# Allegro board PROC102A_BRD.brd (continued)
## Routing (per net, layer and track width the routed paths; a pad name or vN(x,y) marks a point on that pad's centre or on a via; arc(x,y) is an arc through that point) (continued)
EN_PHY_8: length 198.5
  TOP w0.152: v1(100.47,143.59) 100.38,143.51 98.64,143.51 TP30.1
  L03_SIG1 w0.152: v1(100.47,143.59) 100.76,143.59 102.74,141.6 106.94,141.6 108.58,139.96 108.84,139.7 108.84,139.7 109.73,138.81 111.38,138.81 113.41,136.78 113.41,106.65 99.85,93.09 99.85,76.43 103.76,72.52 103.76,57.78 92.76,46.79 92.76,42.3 90.42,39.95 73.84,39.95 71.81,37.92 71.81,37.79 71.55,37.54 71.43,37.54 69.22,35.33 69.22,31.88 66.5,29.16 59.77,29.16 59.13,28.52 46.23,28.52 44.83,29.92 42.67,29.92 41.15,28.4 v1(41.15,26.67)
  BOTTOM w0.152: v1(100.47,143.59) 100.73,143.85 105.44,143.85 107.45,141.85 U34.5 ; U9.25 v1(41.15,26.67)
FAULT_1: length 187.3
  TOP w0.152: v1(126.11,127.25) 123.38,124.52 v1(105.09,124.52)
  L03_SIG1 w0.152: v1(105.09,124.52) 99.56,118.99 79.49,118.99 69.35,108.84 65.48,108.84 61.77,105.13 61.77,90.86 59.06,88.14 52.45,88.14 47.42,83.11 47.42,43.21 37.37,33.16 37.37,26.42 v1(36.93,25.98)
  BOTTOM w0.152: U27.2 132.24,140.66 R76.1 132.12,140.1 131.96,139.93 130.48,139.93 130.22,139.67 130.22,131.36 v1(126.11,127.25) ; U11.45 36.43,26.48 v1(36.93,25.98)
FAULT_2: length 190.2
  TOP w0.152: v1(97.54,119.76) 113.52,119.76 v1(127.53,105.75)
  L03_SIG1 w0.152: v1(36.91,24.79) 36.5,25.2 36.5,32.72 47.12,43.34 47.12,83.95 52.71,89.54 59.31,89.54 61.22,91.44 61.22,105.28 65.79,109.86 69.35,109.86 79.25,119.76 v1(97.54,119.76)
  BOTTOM w0.152: U28.2 132.13,115.2 R77.1 132.01,114.63 131.76,114.38 130.35,114.38 129.54,113.57 129.54,107.76 v1(127.53,105.75) ; U11.44 35.93,25.76 v1(36.91,24.79)
FAULT_3: length 154.4
  L03_SIG1 w0.152: v1(33.93,25.98) 34,25.91 34,24.71 35.47,23.25 52.46,23.25 53.14,23.93 66.8,23.93 68.2,25.32 72.75,25.32 73.99,26.57 73.99,30.48 76.41,32.89 98.17,32.89 128.4,63.12 131.32,63.12 133.35,65.15 133.35,68.45 129.54,72.26 129.54,89.79 130.35,90.6 v1(131.43,90.6)
  BOTTOM w0.152: v1(131.43,90.6) 132.01,90.02 R83.1 132.13,89.8 U30.2 ; v1(33.93,25.98) 33.43,26.48 U11.39
FAULT_4: length 123.1
  L03_SIG1 w0.152: v1(35.41,23.92) 35.77,23.55 51.81,23.55 52.49,24.23 66.65,24.23 68.07,25.65 71.76,25.65 73.66,27.56 73.66,30.58 77.24,34.16 98.55,34.16 129.08,64.69 v1(131.85,64.69)
  BOTTOM w0.152: v1(131.85,64.69) 132.14,64.41 R81.1 132.25,64.02 U29.2 ; v1(35.41,23.92) 35.32,23.92 32.93,26.31 U11.38
FAULT_5: length 127.4
  TOP w0.152: v1(24.89,50.16) 26.54,51.82 26.54,59.66 27.05,60.17 27.05,68.96 27.56,69.47 100.2,69.47 v1(104.27,65.41)
  BOTTOM w0.152: U31.2 106.85,64.02 R89.1 105.23,65.41 v1(104.27,65.41) ; v1(24.89,50.16) 24.89,49.78 27.24,47.44 27.24,41.34 29.93,38.65 U11.32
FAULT_6: length 183.9
  TOP w0.152: v1(104.7,91.59) 99.03,97.36 98.32,98.07 98,98.28 95.97,100.32 v1(90.16,100.32)
  BOTTOM w0.152: v1(90.16,100.32) 90.06,100.21 76.08,100.21 75.06,99.19 70.36,99.19 67.74,96.57 65.28,96.57 58.37,89.66 12.45,89.66 8.85,86.07 8.85,59.77 9.15,59.48 9.15,41.15 25.02,25.27 28.07,25.27 29.43,26.64 U11.31 ; U32.2 106.85,89.93 R88.1 106.74,90.21 106.14,90.8 105.48,90.8 v1(104.7,91.59)
FAULT_7: length 165.2
  L03_SIG1 w0.152: v1(26.96,29.94) 31.78,29.94 34.67,27.05 34.67,26.04 35.16,25.55 35.41,25.55 36.98,23.98 38.46,23.98 39.88,25.4 39.88,27.99 43.08,31.19 47.81,31.19 49.28,29.72 55.5,29.72 55.88,30.1 55.88,31.11 56.62,31.85 59.26,31.85 60.33,30.78 65.86,30.78 67.61,32.53 67.61,37.44 72.77,42.6 72.77,46.38 76.81,50.42 81.48,50.42 91.39,60.33 91.39,109.02 100.29,117.92 105.34,117.92 106.41,116.86 106.41,115.6 v1(106.32,115.52)
  BOTTOM w0.152: v1(26.96,29.94) 26.93,29.92 U11.26 ; U33.2 106.85,114.82 R95.1 106.74,115.11 v1(106.32,115.52)
FAULT_8: length 225.4
  TOP w0.152: v1(44.95,84.21) 85.48,84.21 v1(93.6,92.33)
  L03_SIG1 w0.152: v1(44.95,84.21) 12.17,84.21 9.27,81.31 9.27,58.31 12.85,54.74 25.27,54.74 26.51,53.5 26.51,49.24 24.56,47.29 24.56,37.34 v1(23.59,36.37) ; v1(93.6,92.33) 98.43,92.33 112.9,106.81 112.9,136.4 111,138.3 108.21,138.3 106.12,140.38 v1(106.12,141.09)
  BOTTOM w0.152: U34.2 106.85,140.35 R94.1 106.74,140.48 v1(106.12,141.09) ; U11.25 26.43,29.2 23.59,32.04 v1(23.59,36.37)
GPMC0_AD0: length 26.1
  BOTTOM w0.152: U11.2 37.43,21.5 37.65,21.72 38.48,21.72 38.99,21.21 38.99,17.14 41.02,15.11 46.1,15.11 50.24,10.97 50.24,10.21 51.99,8.46 52.76,8.46 53.1,8.11 J1.E14
GPMC0_AD0_HDR: length 36.7
  BOTTOM w0.152: U11.48 37.93,33.5 35.64,35.79 35.64,35.82 35.59,35.87 35.59,60.86 J6.1
GPMC0_AD1: length 26.3
  BOTTOM w0.152: J1.D14 53.1,6.21 52.45,6.86 52.45,7.37 45.09,14.73 37.59,14.73 36.43,15.89 U11.4
GPMC0_AD1_HDR: length 37.5
  BOTTOM w0.152: U11.47 37.43,33.56 35.26,35.74 35.26,57.09 32.32,60.03 32.32,61.59 J6.3
GPMC0_AD2: length 31.7
  L03_SIG1 w0.152: v1(41.28,16.26) 42.42,16.26 52.45,6.22 v1(52.45,3.94)
  BOTTOM w0.152: v1(41.28,16.26) 39.63,17.91 39.63,21.46 38.7,22.38 37.92,22.38 37.7,22.61 34.8,22.61 34.43,22.24 U11.8 ; v1(52.45,3.94) 52.55,3.94 J1.C14
GPMC0_AD2_HDR: length 39.4
  BOTTOM w0.152: U11.42 34.93,29.09 35.18,29.34 35.97,29.34 36.58,29.94 36.58,33.99 34.95,35.62 34.95,54.46 29.47,59.94 29.47,61.9 J6.5
GPMC0_AD3: length 26.1
  BOTTOM w0.152: J1.E15 51.83,7.35 44.83,14.35 36.7,14.35 33.43,17.62 U11.10
GPMC0_AD3_HDR: length 40.4
  BOTTOM w0.152: J6.7 27.24,61.59 27.24,60.03 34.65,52.62 34.65,35.49 36.21,33.92 36.21,30.01 35.96,29.76 35.04,29.76 34.43,29.15 U11.41
GPMC0_AD4: length 30.2
  BOTTOM w0.152: J1.D15 51.83,5.83 51.18,6.48 51.18,7.57 50.24,8.51 48.52,8.51 43.31,13.72 33.78,13.72 30.93,16.57 U11.15
GPMC0_AD4_HDR: length 39.1
  BOTTOM w0.152: J6.9 23.27,62.05 22.16,60.94 22.16,54.85 29.77,47.24 29.77,41.14 31.43,39.47 U11.35
GPMC0_AD5: length 47.1
  BOTTOM w0.152: U11.17 29.93,21.88 29.34,22.48 27.94,22.48 27.05,23.37 25.78,23.37 25.27,22.86 25.27,16.46 31.66,10.07 31.66,5.75 32.31,5.11 50.88,5.11 51.49,4.49 J1.C15
GPMC0_AD5_HDR: length 39
  BOTTOM w0.152: J6.11 20.73,62.05 21.83,60.94 21.83,54.75 29.47,47.11 29.47,40.59 30.93,39.13 U11.34
GPMC0_AD6: length 31.2
  BOTTOM w0.152: U11.21 27.93,19.85 27.05,18.97 27.05,15.75 30.61,12.19 44.13,12.19 J1.E17
GPMC0_AD6_HDR: length 39.4
  BOTTOM w0.152: U11.29 28.43,38.28 24.7,42.01 24.7,47.33 19.29,52.74 19.29,62.5 18.77,63.02 J6.13
GPMC0_AD7: length 32.3
  BOTTOM w0.152: U11.23 26.93,19.29 26.75,19.1 26.75,15.62 26.93,15.44 30.69,11.68 44.2,11.68 48.59,7.29 48.59,6.46 J1.D17
GPMC0_AD7_HDR: length 39.9
  BOTTOM w0.152: U11.28 27.93,37.72 24.4,41.26 24.4,47.2 17.08,54.51 17.08,60.9 15.65,62.33 J6.15
GPMC0_AD8: length 90.9
  L03_SIG1 w0.152: J6.17 13.94,63.02 14.21,62.75 14.21,58.18 14.99,57.4 25.02,57.4 34.67,47.75 34.67,38.86 25.7,29.89 25.7,16.29 32.49,9.5 34.55,9.5 35.96,8.1 37.41,8.1 37.96,7.54 37.96,5.05 41.7,1.31 v1(42.31,1.31)
  BOTTOM w0.152: J1.A22 v1(42.31,1.31)
GPMC0_AD9: length 104.8
  L03_SIG1 w0.152: v1(43.58,1.31) 43.58,1.93 42.08,3.42 40.86,3.42 38.97,5.31 38.97,8.02 37.97,9.02 35.47,9.02 34.68,9.8 32.62,9.8 26.8,15.62 26.8,21.74 26,22.54 26,22.9 26.11,23 26.11,29.82 35.31,39.02 35.31,64.39 34.16,65.53 13.08,65.53 J6.19
  BOTTOM w0.152: J1.A21 v1(43.58,1.31)
GPMC0_AD10: length 66.2
  TOP w0.152: v1(43.58,2.58) 42.78,3.38 42.78,8.78 38.78,12.77 38.78,31.24 32.25,37.77 32.25,54.48 J7.1
  BOTTOM w0.152: J1.B21 v1(43.58,2.58)
GPMC0_AD11: length 60.3
  TOP w0.152: J7.3 34.57,54.27 34.57,36.34 39.13,31.79 39.13,13.17 43.43,8.86 v1(43.43,7.66)
  BOTTOM w0.508: v1(43.43,7.66) 44.07,7.03 J1.E21
GPMC0_AD12: length 65.4
  TOP w0.152: v1(43.58,3.85) 43.15,4.29 43.15,6.73 43.86,7.45 43.86,8.86 39.43,13.29 39.43,32.37 34.88,36.92 34.88,52.03 J7.5
  BOTTOM w0.152: J1.C21 v1(43.58,3.85)
GPMC0_AD13: length 63.5
  TOP w0.152: v1(43.58,6.39) 44.17,6.99 44.17,8.99 39.74,13.42 39.74,32.91 35.24,37.41 35.24,49.85 J7.7
  BOTTOM w0.152: J1.D21 v1(43.58,6.39)
GPMC0_AD14: length 68.7
  TOP w0.152: J7.9 35.57,47.64 35.57,38.31 40.04,33.84 40.04,14.04 44.47,9.61 44.47,5.76 45.5,4.73 45.5,3.22 44.87,2.58 v1(44.85,2.58)
  BOTTOM w0.152: J1.B20 v1(44.85,2.58)
GPMC0_AD15: length 72.2
  TOP w0.152: J7.11 47.06,56.6 45.04,56.6 35.93,47.49 35.93,38.46 40.35,34.05 40.35,14.45 45.43,9.37 45.43,5.66 46.55,4.54 46.55,1.75 v1(46.12,1.31)
  BOTTOM w0.152: J1.A19 v1(46.12,1.31)
GPMC0_CSN1: length 72
  TOP w0.152: J7.17 52.44,54.35 43.77,54.35 36.61,47.19 36.61,39.22 41.71,34.13 41.71,14.12 46.16,9.66 v1(46.16,7.66)
  BOTTOM w0.508: J1.E19 46.16,7.62 v1(46.16,7.66)
GPMC0_CSN2: length 70.7
  TOP w0.152: J7.13 48.21,55.2 44.15,55.2 36.31,47.35 36.31,38.68 40.65,34.33 40.65,14.74 45.73,9.66 45.73,6.22 45.98,5.96 46.96,5.96 v1(47.39,6.39)
  BOTTOM w0.152: J1.D18 v1(47.39,6.39)
GPMC0_CSN3: length 81.3
  TOP w0.152: J7.15 57.27,61.72 59.38,61.72 59.98,61.12 59.98,58.19 55.13,53.33 43.18,53.33 36.91,47.07 36.91,40.27 42.62,34.57 42.62,25.09 42.06,24.54 42.06,14.2 46.6,9.66 46.6,6.87 46.16,6.44 v1(46.16,6.39)
  BOTTOM w0.508: v1(46.16,6.39) 46.75,5.81 J1.D19
GPMC0_DIR: length 76.2
  TOP w0.152: J7.19 61.25,57.93 54.62,51.3 41.61,51.3 37.22,46.91 37.22,40.77 43.19,34.8 43.19,21.54 42.54,20.89 42.54,14.36 47.33,9.56 47.33,7.72 v1(47.39,7.66)
  BOTTOM w0.152: J1.E18 v1(47.39,7.66)
H_CS: length 114
  TOP w0.152: U35.10 86.4,94.91 R105.1 86.05,94.81 85.62,94.39 v1(85.62,92.85) ; R128.1 v1(118.62,10.76)
  BOTTOM w0.152: v1(118.62,10.76) 117.31,12.06 100.45,12.06 92.2,20.31 92.2,28.27 92.4,28.46 92.4,86.07 v1(85.62,92.85)
H_DIAG: length 5.1
  TOP w0.152: R100.1 90.3,95.97 89,97.27 U35.14
H_FAULT: length 135.4
  TOP w0.152: U12.26 37.43,31.07 27.91,40.59 24.85,40.59 21.86,43.58 21.86,67.96 22.16,68.26 22.16,82.5 27.1,87.45 72.97,87.45 80.32,94.8 R99.2 84.72,95.88 85.75,96.91 U35.9
H_SEH: length 136.1
  TOP w0.152: U12.32 34.43,32.84 28.38,38.9 24,38.9 19.62,43.27 19.62,82.93 24.65,87.95 72.46,87.95 80.11,95.6 82.39,95.6 84.45,97.66 U35.7
H_SEL: length 139.3
  TOP w0.152: v1(35.78,30.19) 34.93,29.34 U12.31 ; U35.8 85.1,97.7 v1(84.45,97.05)
  BOTTOM w0.152: v1(84.45,97.05) 83.68,96.29 73.01,96.29 62.33,85.6 19.18,85.6 17.07,83.49 17.07,77.09 17.08,77.08 17.08,76.14 24.69,68.53 24.69,56.34 32.3,48.73 32.3,43.15 32.04,42.9 32.04,33.93 v1(35.78,30.19)
H_THERM: length 5.8
  TOP w0.152: R98.1 89.04,95.7 v1(89.04,95.7) 88.35,96.39 U35.13
  BOTTOM w0.152: R98.1 89.04,95.7 v1(89.04,95.7)
HSE_DETECT: length 4.9
  BOTTOM w0.152: J1.E4 67.08,8.31 R1.2
HSE_GPIO0_31: length 22.7
  TOP w0.152: U12.15 33.43,15.47 40.53,8.38 40.53,5.58 41.67,4.44 41.67,3.23 v1(42.31,2.58)
  BOTTOM w0.152: J1.B22 v1(42.31,2.58)
HSE_GPIO0_31_HDR: length 31.7
  TOP w0.152: U12.35 32.93,29.07 33.76,29.9 33.76,31.08 27.3,37.53 16.73,37.53 10.55,43.72 J8.1
HSE_GPIO0_32: length 21.5
  TOP w0.152: U12.17 34.43,19.85 33.91,19.32 33.91,15.67 41.51,8.07 41.51,5.7 42.31,4.91 v1(42.31,3.85)
  BOTTOM w0.152: J1.C22 v1(42.31,3.85)
HSE_GPIO0_32_HDR: length 29.4
  TOP w0.152: J8.3 18.82,38.02 27.24,38.02 34.09,31.18 34.09,29.67 33.43,29.01 U12.34
HSE_GPIO0_33: length 17.7
  TOP w0.152: v1(42.31,6.39) 41.85,6.85 41.85,8.11 41.82,8.15 41.82,8.2 37.49,12.52 37.49,18.62 36.43,19.68 U12.21
  BOTTOM w0.152: J1.D22 v1(42.31,6.39)
HSE_GPIO0_33_HDR: length 53.5
  TOP w0.152: J8.5 14.43,44.95 14.43,47.3 13.83,47.9 10.25,47.9 9.3,46.96 9.3,40.16 25.11,24.36 35.59,24.36 35.93,24.7 U12.29
HSE_GPIO0_34: length 21.9
  TOP w0.152: v1(41.04,3.85) 40.2,4.69 40.2,8.18 30.93,17.44 U12.10
  BOTTOM w0.152: J1.C23 v1(41.04,3.85)
HSE_GPIO0_34_HDR: length 22.6
  TOP w0.152: v1(20.83,36.96) 24.6,36.96 29.93,31.62 U12.41
  BOTTOM w0.152: v1(20.83,36.96) 20.83,37.31 18.19,39.95 J8.7
HSE_GPIO0_35: length 24.5
  TOP w0.152: v1(39.77,2.58) 39.03,3.32 39.03,7.74 29.16,17.61 28.62,17.61 27.64,18.59 27.64,19.35 27.93,19.65 U12.4
  BOTTOM w0.152: J1.B24 v1(39.77,2.58)
HSE_GPIO0_35_HDR: length 18.5
  TOP w0.152: v1(25.13,31.76) 25.13,31.08 26.93,29.28 U12.47
  BOTTOM w0.152: v1(25.13,31.76) 25.66,32.29 25.66,37.14 20.73,42.07 J8.9
HSE_GPIO0_36: length 38.1
  TOP w0.152: U12.2 26.93,21.71 26.42,22.22 25.53,22.22 25.15,21.84 25.15,17.78 25.91,17.02 29.32,17.02 38.03,8.31 38.03,2.37 38.54,1.87 44.3,1.87 v1(44.85,1.31)
  BOTTOM w0.152: J1.A20 v1(44.85,1.31)
HSE_GPIO0_36_HDR: length 18.2
  TOP w0.152: v1(22.07,36.48) 22.68,35.87 22.68,32.93 25.53,30.08 25.53,28.57 25.89,28.22 U12.48
  L03_SIG1 w0.152: J8.11 22.05,42.52 22.05,36.48 22.06,36.48 v1(22.07,36.48)
HSE_GPIO0_37: length 21.8
  TOP w0.152: U12.8 29.93,19.66 30.46,19.13 30.46,17.14 39.34,8.27 39.34,4.29 v1(39.77,3.85)
  BOTTOM w0.152: J1.C24 v1(39.77,3.85)
HSE_GPIO0_37_HDR: length 18.2
  TOP w0.152: U12.42 29.43,31.39 v1(24.41,36.41)
  L03_SIG1 w0.152: v1(24.41,36.41) 25.81,37.8 J8.13
HSE_GPIO0_38: length 53.8
  L03_SIG1 w0.152: v1(37.23,7.66) 37.66,7.23 37.66,3.68 37.41,3.42 36.33,3.42 35.5,4.26 35.5,6.2 33.17,8.52 32.18,8.52 24.6,16.1 24.6,35.29 28.35,39.04 J8.15
  BOTTOM w0.152: J1.E26 v1(37.23,7.66)
HSE_GPIO0_39: length 49.4
  L03_SIG1 w0.152: J8.17 30.89,40.86 26.16,36.14 26.16,32.19 24.9,30.93 24.9,16.22 32.24,8.89 34.07,8.89 36.38,6.58 36.38,4.7 v1(37.23,3.85)
  BOTTOM w0.152: J1.C26 v1(37.23,3.85)
HSE_GPIO0_41: length 47.8
  L03_SIG1 w0.152: v1(37.23,6.39) 34.43,9.19 32.36,9.19 25.21,16.35 25.21,30.67 26.67,32.13 26.67,36.15 33.43,42.9 J8.19
  BOTTOM w0.152: J1.D26 v1(37.23,6.39)
HSE_MCAN0_RX/UART4_TXD: length 186.9
  L03_SIG1 w0.152: v1(39.77,7.66) 41.97,5.46 50.04,5.46 52.08,3.42 52.7,3.42 54.17,4.89 54.17,12.76 53.09,13.84 53.09,17.02 55.32,19.25 62.03,19.25 62.83,18.45 62.83,15.52 63.3,15.06 67,15.06 68.69,16.75 68.69,18.23 70.96,20.49 78.86,20.49 81.8,23.43 86.05,23.43 v1(86.62,22.86)
  BOTTOM w0.152: J1.E24 v1(39.77,7.66) ; J3.19 40.85,82.42 90.17,82.42 90.55,82.04 90.55,41.02 86.62,37.08 v1(86.62,22.86)
HSE_MCAN0_TX/UART4_RXD: length 182.6
  L03_SIG1 w0.152: v1(39.77,6.39) 41.31,4.85 50.14,4.85 51.87,3.12 53.79,3.12 54.36,3.68 54.36,4.65 54.47,4.77 54.47,12.96 53.98,13.46 53.98,17.47 55.45,18.95 61.9,18.95 62.46,18.39 62.46,15.46 63.17,14.75 67.12,14.75 69,16.63 69,18.1 71,20.11 78.91,20.11 81.92,23.12 84.58,23.12 v1(85.35,22.35)
  BOTTOM w0.152: J1.D24 v1(39.77,6.39) ; J3.17 42.75,81.79 89.92,81.79 90.25,81.46 90.25,42.49 85.35,37.59 v1(85.35,22.35)
HSE_MCAN1_RX/I2C3_SDA: length 104
  TOP w0.152: v1(23.12,52.58) 23.12,57.9 22.16,58.85 22.16,65.59 26.93,70.36 32.88,70.36 36.07,73.54 36.07,81.03 36.7,81.66 41.53,81.66 43.23,79.97 J3.15
  L03_SIG1 w0.152: v1(23.12,52.58) 19.31,48.77 19.31,34.85 23.99,30.17 23.99,12.38 31.23,5.14 32.13,5.14 v1(33.42,3.85)
  BOTTOM w0.152: J1.C29 v1(33.42,3.85)
HSE_MCAN1_TX/I2C3_SCL: length 100.1
  TOP w0.152: J3.13 44.71,78.66 44.71,76.84 37.64,69.77 27.36,69.77 24.51,66.93 24.51,60.21 25.27,59.45 v1(25.27,53.09)
  L03_SIG1 w0.152: v1(33.42,6.39) 32.99,5.96 30.84,5.96 24.29,12.51 24.29,30.48 19.62,35.16 19.62,46.73 20.27,47.38 20.58,47.38 25.27,52.07 v1(25.27,53.09)
  BOTTOM w0.152: J1.D29 v1(33.42,6.39)
IN+: length 3
  TOP w0.152: U39.17 81.05,132.35 81.16,132.46 81.59,132.46 81.71,132.33 81.71,131.25 U39.16
IN-: length 3
  TOP w0.152: U39.4 81.05,126.57 81.21,126.73 81.55,126.73 81.7,126.57 U39.5
IN_CS: length 135.8
  TOP w0.152: U39.13 v1(83.65,132.82) ; R126.2 103.91,13.06 v1(103.89,13.08)
  BOTTOM w0.152: v1(83.65,132.82) 83.65,128.18 91.82,120.01 91.82,106.17 95.51,102.49 95.51,89.79 92.81,87.1 92.81,86.52 93.01,86.33 93.01,28.21 92.81,28.01 92.81,23.3 103.03,13.08 v1(103.89,13.08)
L+_1: length 1.7
  TOP w0.381: U36.17 73.13,106.45 72.77,106.81
  vias: v1(72.85,111.2) v1(72.85,110.19) v1(72.85,109.17) v1(72.85,108.16)
L+_2:
  vias: v1(78.25,105.93) v1(78.25,104.92) v1(79.27,105.93) v1(79.27,104.92)
L+_3: length 1.4
  TOP w0.381: U36.26 67.28,106.57 67.22,106.63
  vias: v1(64.59,107.34) v1(65.61,107.34) v1(66.63,107.34) v1(67.64,107.34)
L+_4:
  vias: v1(63.7,105.76) v1(63.7,104.74) v1(64.71,105.76) v1(64.71,104.74)
L+_5:
  vias: v1(87.14,110.16) v1(88.16,110.16) v1(89.18,110.16) v1(90.19,110.16)
L+_6: length 1.2
  TOP w0.381: U35.16 88.35,106.16 88.54,106.35
  vias: v1(92.4,102.8) v1(92.4,101.79) v1(93.41,102.8) v1(93.41,101.79)
L+_7: length 1.7
  TOP w0.381: 82.29,106.83 81.85,106.39 U35.26
  vias: v1(82.29,111.53) v1(82.29,110.38) v1(82.29,109.11) v1(82.29,107.97)
L+_8:
  vias: v1(76.59,108.89) v1(76.59,107.88) v1(77.61,108.89) v1(77.61,107.88)
L_CS: length 115.8
  TOP w0.152: U36.10 71.83,94.91 R108.1 71.89,94.81 71.05,93.97 v1(71.05,92.85) ; R127.2 v1(107.19,10.92)
  BOTTOM w0.152: v1(107.19,10.92) 106.68,10.41 100.59,10.41 91.59,19.41 91.59,28.52 91.79,28.71 91.79,82.58 83.06,91.31 72.59,91.31 v1(71.05,92.85)
L_DIAG: length 5.1
  TOP w0.152: R103.1 75.73,95.97 74.43,97.27 U36.14
L_FAULT: length 134.9
  TOP w0.152: v1(68.96,95.32) 69.48,94.8 R102.2 71.18,95.83 U36.9 ; v1(27.47,30.38) 27.93,29.92 U12.45
  BOTTOM w0.152: v1(27.47,30.38) 27.47,37.54 22.16,42.84 22.16,47.33 9.46,60.03 9.46,85.28 12.83,88.65 17.48,88.65 17.53,88.7 58.73,88.7 64.52,94.49 68.13,94.49 v1(68.96,95.32)
L_SEH: length 124.7
  TOP w0.152: v1(32.02,31.9) 31.43,31.31 U12.38 ; U36.7 69.88,96.89 67.3,94.32 v1(67.3,93.02)
  BOTTOM w0.152: v1(32.02,31.9) 31.74,32.18 31.74,43.02 31.99,43.27 31.99,48.6 24.39,56.21 24.39,67.56 16.77,75.18 16.77,84.58 18.92,86.74 61.02,86.74 v1(67.3,93.02)
L_SEL: length 135.1
  TOP w0.152: v1(70.33,96.79) 70.43,96.79 70.53,96.89 U36.8 ; U12.44 28.43,30.7 27.93,31.2 v1(26.37,31.2)
  BOTTOM w0.152: v1(26.37,31.2) 26.37,37.52 21.86,42.03 21.86,47.2 9.16,59.9 9.16,85.86 12.45,89.15 58.29,89.15 65.41,96.27 69.81,96.27 v1(70.33,96.79)
L_THERM: length 5.8
  TOP w0.152: U36.13 73.78,96.39 v1(74.47,95.7) 74.47,95.7 R101.1
  BOTTOM w0.152: v1(74.47,95.7) 74.47,95.7 R101.1
LATCH: length 65.7
  TOP w0.152: v1(93.85,25.91) 81.66,25.91 79.35,23.59 75.67,23.59 74.89,24.38 U17.39 ; U26.4 127.62,33.64 v1(126.37,32.38)
  BOTTOM w0.152: v1(93.85,25.91) 93.85,27.76 96.99,30.9 111.29,30.9 113.54,33.15 125.6,33.15 v1(126.37,32.38)
LED_G1: length 109.4
  TOP w0.152: U26.20 137.86,33.01 139.27,34.42 139.27,129.87 144.99,135.59 LD21.1
LED_G2: length 86
  TOP w0.152: U26.18 138.32,31.74 141.1,34.51 141.1,106.81 145,110.71 LD19.1
LED_G3: length 61.6
  TOP w0.152: U26.16 139.04,30.47 142.37,33.79 142.37,60.58 143.26,61.47 143.26,82.8 145.12,84.66 LD17.1
LED_G4: length 38
  TOP w0.152: LD15.1 145.33,59.6 143.38,57.66 143.38,32.97 139.61,29.2 U26.14
LED_G5: length 50.7
  TOP w0.152: U26.12 v1(128.48,28.56) ; LD13.1 v1(98.03,55.75)
  BOTTOM w0.152: v1(98.03,55.75) 104,49.78 116.08,49.78 129.64,36.22 129.64,29.72 v1(128.48,28.56)
LED_G6: length 75
  TOP w0.152: U26.10 v1(128.48,29.83) ; LD11.1 v1(98.03,81.15)
  BOTTOM w0.152: v1(128.48,29.83) 128.48,29.91 129.29,30.71 129.29,35.94 116.59,48.64 104.38,48.64 97.55,55.47 97.55,80.67 v1(98.03,81.15)
LED_G7: length 101
  TOP w0.152: U26.8 v1(128.48,31.1) ; LD9.1 v1(98.03,106.55)
  BOTTOM w0.152: v1(128.48,31.1) 127.89,31.69 127.89,35.56 117.22,46.23 102.49,46.23 96.27,52.45 96.27,83.49 98.03,85.25 v1(98.03,106.55)
LED_G8: length 120.7
  TOP w0.152: U26.6 131.94,32.37 132.08,32.51 v1(132.34,32.51) ; LD7.1 v1(98.78,131.5)
  BOTTOM w0.152: v1(98.78,131.5) 98.78,130.07 102.24,126.62 109.86,126.62 118.75,117.73 118.75,93.6 120.27,92.08 120.27,48.64 131.45,37.46 131.45,33.27 132.21,32.51 v1(132.34,32.51)
LED_R1: length 106.6
  TOP w0.152: U26.19 138.08,32.37 140.71,35 140.71,127.76 145.06,132.11 LD20.1
LED_R2: length 83.1
  TOP w0.152: U26.17 138.55,31.1 141.73,34.28 141.73,103.76 144.95,106.98 LD18.1
LED_R3: length 59
  TOP w0.152: U26.15 139.4,29.83 142.88,33.31 142.88,59.94 143.89,60.96 143.89,79.76 145.65,81.51 LD16.1
LED_R4: length 35.2
  TOP w0.152: U26.13 139.99,28.56 143.89,32.46 143.89,54.48 145.46,56.05 LD14.1
LED_R5: length 56.6
  TOP w0.152: LD12.1 v1(98.03,59.15) ; v1(127.46,28.56) 128.1,29.2 U26.11
  BOTTOM w0.152: v1(127.46,28.56) 127.47,28.56 128.05,27.98 128.77,27.98 129.95,29.16 129.95,35.89 129.95,36.55 115.7,50.8 105.28,50.8 98.03,58.05 v1(98.03,59.15)
LED_R6: length 81.2
  TOP w0.152: U26.9 128.1,30.47 v1(127.46,29.83) ; LD10.1 v1(98.03,84.55)
  BOTTOM w0.152: v1(98.03,84.55) 96.9,83.42 96.9,53.98 103.38,47.5 116.59,47.5 128.22,35.86 128.22,32.31 128.91,31.62 128.91,30.77 128.54,30.4 128.02,30.4 127.46,29.85 v1(127.46,29.83)
LED_R7: length 107.1
  TOP w0.152: v1(127.46,31.1) 128.1,31.74 U26.7 ; LD8.1 96.91,110.92 v1(97.05,111.06)
  BOTTOM w0.152: v1(97.05,111.06) 97.55,110.56 97.55,85.78 95.6,83.82 95.6,52.11 102.74,44.96 117.73,44.96 127.46,35.22 v1(127.46,31.1)
LED_R8: length 135.9
  TOP w0.152: U26.5 128.1,33.01 126.37,31.27 v1(126.37,31.24) ; LD6.1 98.53,134.9 99.7,133.73 99.7,128.14 97.92,126.37 v1(95.97,126.37)
  BOTTOM w0.152: v1(126.37,31.24) 126.8,31.67 126.8,35.26 117.98,44.07 102.11,44.07 95.29,50.89 95.29,84.84 96.96,86.5 96.96,102.81 95.97,103.81 v1(95.97,126.37)
LOAD_PULSE_SE: length 85.2
  TOP w0.152: v1(33.49,24.92) 31.52,24.92 30.93,25.51 U12.39 ; R121.1 v1(104.86,15.28)
  L03_SIG1 w0.152: v1(104.86,15.28) 96.1,24.03 79.41,24.03 78.87,23.5 78.47,23.5 77.34,22.36 77.34,21.97 76.58,21.21 56.01,21.21 54.61,22.61 53.04,22.61 52.81,22.38 35.26,22.38 33.49,24.16 v1(33.49,24.92)
MCU_PORZ: length 79.5
  TOP w0.152: TP33.1 J18.6
  L03_SIG1 w0.152: J18.6 86.99,20.7 87.76,21.46 87.76,23.11 87.5,23.37 86.94,23.37 86.57,23.73 80.71,23.73 79.32,22.34 79.32,22.12 78.1,20.9 54.26,20.9 53.65,21.51 53.29,21.51 52.68,20.9 41.99,20.9 33.4,12.32 33.4,11.56 32.81,10.97 v1(32.27,10.97)
  BOTTOM w0.152: J1.E30 32.27,7.54 v1(32.27,10.97)
MCU_RESETSTATZ: length 24.2
  TOP w0.152: TP32.1 J18.4
  L03_SIG1 w0.152: J18.4 70.53,10.49 v1(67.71,7.66)
  BOTTOM w0.152: J1.E3 v1(67.71,7.66)
MCU_RESETZ: length 24.2
  TOP w0.152: TP31.1 J18.2
  L03_SIG1 w0.152: v1(67.71,6.39) 67.92,6.39 70.11,8.59 86.35,8.59 J18.2
  BOTTOM w0.152: J1.D3 v1(67.71,6.39)
MUX_CONTROL_1: length 82.3
  TOP w0.152: U12.24 37.93,22.25 38.1,22.42 v1(38.1,22.82) 37.8,23.11 26.83,23.11 v1(26.43,22.72) ; R72.1 85.55,18.19 v1(83.3,20.43) 83.3,20.42 82.94,20.05 82.11,20.05 81.89,20.28 U17.24 ; U7.24 v1(67.24,22.05)
  BOTTOM w0.152: 70.11,22.48 70.39,22.2 U2.24 ; 70.11,22.48 69.67,22.05 v1(67.24,22.05) 67.64,22.45 67.64,23.19 67.3,23.53 57.31,23.53 56.26,22.48 ; 70.11,22.48 72.73,25.1 81.01,25.1 83.3,22.81 v1(83.3,20.43) ; 56.26,22.48 56.14,22.61 41.94,22.61 41.15,21.82 ; 56.26,22.48 55.74,21.96 U4.24 ; 41.15,21.82 40.15,22.82 v1(38.1,22.82) ; 41.15,21.82 U9.24 ; U11.24 v1(26.43,22.72)
Net_3: length 0.9
  BOTTOM w0.152: 35.32,4.49 v1(34.69,3.85)
Net_5: length 0.9
  BOTTOM w0.152: 35.32,5.76 v1(34.69,6.39)
Net_6: length 0.9
  BOTTOM w0.152: 34.05,3.22 v1(33.42,2.58)
PRG0_HSE_ETH1_CLK: length 55.3
  TOP w0.152: J18.3 89.57,10.52 TP35.1
  L03_SIG1 w0.152: J18.3 90.52,10.49 91.43,9.58 91.43,5.73 87.68,1.98 67.45,1.98 67.04,1.58 67.04,1.17 66.41,0.53 51.31,0.53 51.31,0.54 50.11,1.75 49.09,1.75 v1(48.66,1.31)
  BOTTOM w0.152: J1.A17 v1(48.66,1.31)
PRG0_HSE_ETH2_CLK: length 48.6
  TOP w0.152: J18.1 89.59,8 TP34.1
  L03_SIG1 w0.152: v1(48.66,2.58) 48.66,2.54 49.1,2.1 50.48,2.1 51.74,0.84 65.74,0.84 66.01,1.11 66.01,1.53 67.53,3.05 74.33,3.05 74.89,2.49 84.08,2.49 J18.1
  BOTTOM w0.152: J1.B17 v1(48.66,2.58)
PRG0_MDIO0_MDC: length 129.6
  TOP w0.152: v1(65.17,1.31) 65.69,1.83 65.69,15.44 68.81,18.56 68.81,35.86 63.78,40.88 63.78,66.9 62.61,68.07 v1(44.32,68.07)
  L03_SIG1 w0.152: v1(44.32,68.07) 20.7,68.07 11.69,77.09 11.69,78.71 J5.19
  BOTTOM w0.152: J1.A5 v1(65.17,1.31)
PRG0_MDIO0_MDIO: length 127.7
  TOP w0.152: v1(43.69,68.96) 62.36,68.96 64.75,66.57 64.75,40.35 69.11,35.98 69.11,18.4 66.01,15.29 66.01,1.75 v1(66.44,1.31)
  L03_SIG1 w0.152: J5.17 14.35,78.58 14.35,76.71 22.1,68.96 v1(43.69,68.96)
  BOTTOM w0.152: J1.A4 v1(66.44,1.31)
PRG0_PRU0GPO0: length 79.6
  TOP w0.152: Q1.1 115.01,33.74 R69.1 114.96,33.23 110.81,29.09 106.94,29.09 102.13,24.28 84.69,24.28 v1(82.79,22.38)
  L03_SIG1 w0.152: v1(56.28,2.58) 56.71,2.15 57.71,2.15 58.86,3.3 61.42,3.3 64.39,6.28 64.39,10.73 72.82,19.16 79.57,19.16 v1(82.79,22.38)
  BOTTOM w0.152: J1.B12 v1(56.28,2.58) ; U2.2 81.39,22.03 81.8,22.44 82.74,22.44 v1(82.79,22.38)
PRG0_PRU0GPO0_HDR: length 58
  BOTTOM w0.152: U2.48 81.89,38.1 77.84,42.15 77.84,65.34 88,75.5 88,79.15 J2.1
PRG0_PRU0GPO1: length 33.3
  BOTTOM w0.152: J1.E8 62.11,8.42 62.11,15.57 62.51,15.97 64.92,15.97 65.92,14.97 79.1,14.97 80.39,16.25 U2.4
PRG0_PRU0GPO1_HDR: length 57.9
  BOTTOM w0.152: J2.3 87.68,79.16 87.68,75.84 77.54,65.7 77.54,41.91 81.39,38.06 U2.47
PRG0_PRU0GPO2: length 33.3
  L03_SIG1 w0.152: v1(78.59,17.44) 79.21,17.44 79.5,17.14 79.5,16.28 78.59,15.37 74.8,15.37 66.97,7.54 66.97,3.76 64.99,1.78 61.82,1.78 v1(61.36,1.31)
  BOTTOM w0.152: J1.A8 v1(61.36,1.31) ; v1(78.59,17.44) 78.16,17.87 78.16,19.85 78.39,20.08 U2.8
PRG0_PRU0GPO2_HDR: length 56.8
  BOTTOM w0.152: U2.42 78.89,38.78 75.29,42.37 75.29,68.29 82.92,75.92 82.92,79.15 J2.5
PRG0_PRU0GPO3: length 32.7
  L03_SIG1 w0.152: v1(78.57,16.53) 75.53,16.53 66.01,7 66.01,4.28 64.74,3.01 64.74,2.38 64.44,2.08 61.69,2.08 61.36,1.75 60.52,1.75 v1(60.09,1.31)
  BOTTOM w0.152: U2.10 77.39,17.72 v1(78.57,16.53) ; J1.A9 v1(60.09,1.31)
PRG0_PRU0GPO3_HDR: length 56.9
  BOTTOM w0.152: J2.7 82.6,79.16 82.6,76.35 74.99,68.74 74.99,42.24 78.58,38.65 78.58,29.56 78.39,29.36 U2.41
PRG0_PRU0GPO4: length 34.3
  L03_SIG1 w0.152: v1(75.73,17.57) 73.33,17.57 64.74,8.98 64.74,5.68 63.06,4 63.06,3.68 62.3,2.92 59.95,2.92 58.8,1.78 57.79,1.78 57.32,1.31 v1(55.01,1.31)
  BOTTOM w0.152: U2.15 74.89,18.41 v1(75.73,17.57) ; J1.A13 v1(55.01,1.31)
PRG0_PRU0GPO4_HDR: length 55.3
  BOTTOM w0.152: U2.35 75.39,39.51 72.77,42.13 72.77,70.57 77.73,75.53 77.73,79.04 J2.9
PRG0_PRU0GPO5: length 22.6
  L03_SIG1 w0.152: v1(63.9,3.85) 65.7,5.66 65.7,7.35 74.11,15.76 v1(74.11,16.43)
  BOTTOM w0.152: v1(74.11,16.43) 74.11,16.46 74.25,16.6 74.25,19.88 73.89,20.24 U2.17 ; J1.C6 v1(63.9,3.85)
PRG0_PRU0GPO5_HDR: length 54.3
  BOTTOM w0.152: J2.11 75.16,79.01 75.16,74.34 72.46,71.64 72.46,42 74.89,39.58 U2.34
PRG0_PRU0GPO6: length 25.2
  L03_SIG1 w0.152: v1(61.22,13.97) 61.39,13.79 61.39,6.43 v1(61.36,6.39)
  BOTTOM w0.152: v1(61.22,13.97) 61.22,15.51 62.09,16.38 64.69,16.38 64.7,16.38 70.76,16.38 71.89,17.51 U2.21 ; J1.D8 v1(61.36,6.39)
PRG0_PRU0GPO6_HDR: length 54.1
  BOTTOM w0.152: J2.13 72.62,79.01 72.62,73.91 70.23,71.52 70.23,42.34 72.39,40.18 U2.29
PRG0_PRU0GPO7: length 25.2
  TOP w0.152: v1(66.28,17.27) 66.28,17.01 64.33,15.07 64.33,4.91 62.63,3.2 v1(62.63,2.58)
  BOTTOM w0.152: U2.23 70.89,17.87 70.28,17.27 v1(66.28,17.27) ; J1.B7 v1(62.63,2.58)
PRG0_PRU0GPO7_HDR: length 53.1
  BOTTOM w0.152: J2.15 69.92,78.85 69.92,42.09 71.89,40.13 U2.28
PRG0_PRU0GPO8: length 27.3
  TOP w0.152: v1(67.21,23.01) 67.69,22.53 67.69,17.94 64.63,14.89 64.63,3.94 62.63,1.93 v1(62.63,1.31)
  BOTTOM w0.152: J1.A7 v1(62.63,1.31) ; v1(67.21,23.01) 66.74,22.54 U4.2
PRG0_PRU0GPO8_HDR: length 52.6
  BOTTOM w0.152: J2.17 67.68,79.15 67.68,30.83 67.24,30.39 U4.48
PRG0_PRU0GPO11: length 31.1
  L03_SIG1 w0.152: v1(52.45,2.58) 53.77,2.58 54.57,3.39 55.16,3.39 55.44,3.68 55.44,5.15 55.89,5.59 55.89,15.88 57.63,17.63 60.12,17.63 v1(60.93,16.81)
  BOTTOM w0.152: v1(60.93,16.81) 62.08,16.81 62.1,16.83 62.97,16.83 63.77,17.63 65.51,17.63 65.74,17.86 U4.4 ; v1(52.45,2.58) 52.47,2.58 J1.B14
PRG0_PRU0GPO11_HDR: length 52.7
  BOTTOM w0.152: J2.19 67.38,79.14 67.38,31.06 66.74,30.43 U4.47
PRG0_PRU0GPO12: length 26.7
  L03_SIG1 w0.152: v1(53.74,1.31) 54.17,1.75 54.17,2.35 54.87,3.05 55.24,3.05 55.74,3.55 55.74,4.69 56.42,5.37 56.42,8.35 56.42,14.64 v1(57.28,15.49)
  BOTTOM w0.152: v1(57.28,15.49) 59.01,15.49 60.79,17.27 62.36,17.27 63.74,18.66 U4.8 ; J1.A14 v1(53.74,1.31)
PRG0_PRU0GPO12_HDR: length 54
  BOTTOM w0.152: U4.42 64.24,29.29 64.48,29.52 64.48,71.37 60.14,75.7 60.14,78.86 J3.1
PRG0_PRU0GPO13: length 25.3
  L03_SIG1 w0.152: v1(59.05,17.04) 59.22,17.04 63.89,12.37 63.89,6.87 62.12,5.09 v1(61.6,5.09)
  BOTTOM w0.152: U4.10 62.74,18.16 62.15,17.58 60.66,17.58 60.14,17.06 59.06,17.06 v1(59.05,17.04) ; v1(61.6,5.09) 63.93,5.09 J1.C5
PRG0_PRU0GPO13_HDR: length 54.1
  BOTTOM w0.152: J3.3 59.84,78.84 59.84,75.44 64.17,71.1 64.17,29.65 63.74,29.22 U4.41
PRG0_PRU0GPO14: length 22.1
  L03_SIG1 w0.152: v1(58.08,17.19) 59.61,15.67 60.13,15.67 61.79,14.01 61.79,6.22 60.09,4.51 v1(60.09,3.85)
  BOTTOM w0.152: U4.15 60.24,17.95 59.77,17.47 58.36,17.47 v1(58.08,17.19) ; J1.C9 v1(60.09,3.85)
PRG0_PRU0GPO14_HDR: length 56.5
  BOTTOM w0.152: U4.35 60.74,29.27 61.79,30.32 61.79,32.69 63.27,34.16 63.27,67.57 55.06,75.77 55.06,78.86 J3.5
PRG0_PRU0GPO15: length 18
  BOTTOM w0.152: J1.D12 56.31,6.43 56.31,16.69 57.4,17.78 59.24,17.78 59.69,18.23 59.69,19.38 59.24,19.83 U4.17
PRG0_PRU0GPO15_HDR: length 56.6
  BOTTOM w0.152: J3.7 54.74,78.85 54.74,75.67 62.96,67.44 62.96,35.91 60.71,33.66 60.71,29.84 60.24,29.37 U4.34
PRG0_PRU0GPO16: length 20.6
  TOP w0.152: v1(60.19,7.77) 60.19,7.74 59.31,6.86 57.91,6.86 57.02,7.75 57.02,10.29 54.1,13.21 54.1,14.82 v1(54.7,15.41)
  BOTTOM w0.152: U4.21 57.24,18.05 54.7,15.5 v1(54.7,15.41) ; J1.E9 v1(60.19,7.77)
PRG0_PRU0GPO16_HDR: length 59.4
  BOTTOM w0.152: J3.9 49.98,78.86 49.98,76.8 62.66,64.13 62.66,37.46 58.18,32.98 58.18,29.72 57.74,29.29 U4.29
PRG0_PRU0GPO17: length 29
  TOP w0.152: v1(52.34,9.41) 52.34,6.06 54.28,4.12 54.28,3.76 55.07,2.97 55.3,2.97 55.85,2.42 55.85,2.41 56.1,2.15 56.12,2.15 56.19,2.08 59.18,2.08 60.01,2.91 60.62,2.91 61.05,2.48 v1(61.46,2.48)
  BOTTOM w0.152: J1.B8 v1(61.46,2.48) ; v1(52.34,9.41) 52.45,9.53 52.58,9.53 52.83,9.78 52.83,14.22 56.24,17.63 U4.23
PRG0_PRU0GPO17_HDR: length 59.5
  BOTTOM w0.152: U4.28 57.24,29.37 57.87,30 57.87,33.11 62.35,37.59 62.35,63.93 49.66,76.63 49.66,78.85 J3.11
PRG0_PRU0GPO18: length 49.2
  TOP w0.152: v1(60.19,2.48) 60.19,2.4 59.56,1.78 50.12,1.78 49.15,2.75 49.15,11.68 46.86,13.97 46.61,13.97 44.25,16.33 43.31,16.33 43.06,16.58 43.06,17.52 43.05,17.53 43.05,18.67 45.21,20.83 50.55,20.83 51.82,22.1 52.68,22.1 53.06,21.72 53.81,21.72 54.5,22.4 56.59,22.4 57.05,21.95 57.05,21.95 57.24,21.75 U7.4
  BOTTOM w0.152: J1.B9 v1(60.19,2.48)
PRG0_PRU0GPO18_HDR: length 26.7
  TOP w0.152: U7.47 56.14,28.44 56.14,32.64 53.18,35.59 46.59,35.59 J4.1
PRG0_PRU0GPO19: length 25.2
  TOP w0.152: U7.8 59.24,20 56.39,17.14 56.39,15.19 56.57,15.01 56.57,14.05 61.6,9.02 61.6,7.29 57.73,3.42 56.71,3.42 v1(56.18,3.96)
  BOTTOM w0.152: J1.B11 v1(56.18,3.96)
PRG0_PRU0GPO19_HDR: length 26.9
  TOP w0.152: J4.3 44.75,39.97 51.6,39.97 58.23,33.34 58.23,29.66 58.74,29.15 U7.42
PRG0_PRU1GPO0: length 92.3
  TOP w0.152: Q2.1 109.33,33.81 R70.1 v1(109.28,32.84) ; v1(57.44,22.83) 62.51,22.83 62.74,22.61 62.74,20.83 U7.15 62.74,17.91 62.1,17.27 60.2,17.27 59.44,16.51 57.33,16.51 v1(57.24,16.42)
  L03_SIG1 w0.152: v1(109.28,32.84) 101.08,24.64 97.33,24.64 97.33,24.64 93.09,24.64 92.97,24.76 78.61,24.76 77.03,23.18 71.69,23.18 70.13,21.62 66.93,21.62 66.68,21.87 66.68,22.22 66.07,22.83 v1(57.44,22.83) ; v1(57.24,16.42) 58.04,15.62 58.04,14.35 56.73,13.04 56.73,8.35 56.73,3.64 56.1,3.02 56.1,3.02 55.62,2.54 v1(55.12,2.54)
  BOTTOM w0.152: J1.A12 55.12,2.47 v1(55.12,2.54)
PRG0_PRU1GPO0_HDR: length 29
  TOP w0.152: U7.35 62.24,29.39 62.89,30.04 62.89,33.25 55.65,40.48 46.78,40.48 J4.5
PRG0_PRU1GPO1: length 23.6
  TOP w0.152: v1(58.42,16) 61.6,16 63.37,17.78 63.37,19.56 63.74,19.93 U7.17
  L03_SIG1 w0.152: v1(58.42,16) 58.42,12.83 58.08,12.49 58.08,3.13 v1(57.53,2.58)
  BOTTOM w0.152: J1.A11 57.53,2.57 v1(57.53,2.58)
PRG0_PRU1GPO1_HDR: length 27.1
  TOP w0.152: U7.34 62.74,29.28 63.19,29.73 63.19,34.03 55.97,41.24 48.55,41.24 J4.7
PRG0_PRU1GPO2: length 22.7
  TOP w0.152: v1(60.09,6.39) 60.52,6.83 60.55,6.83 61.22,7.49 61.22,8.64 56.26,13.59 56.26,14.89 54.23,16.92 54.23,20.99 54.27,21.03 54.27,21.37 54.99,22.1 55.98,22.1 56.24,21.84 U7.2
  BOTTOM w0.152: J1.D9 v1(60.09,6.39)
PRG0_PRU1GPO2_HDR: length 18.5
  TOP w0.152: U7.48 55.77,28.35 55.77,31.84 v1(54.22,33.39)
  BOTTOM w0.152: J4.9 48.55,39.06 v1(54.22,33.39)
PRG0_PRU1GPO3: length 20.8
  TOP w0.152: U7.21 65.74,18.12 65.4,17.78 63.88,17.78 62.92,16.81 62.92,8.37 63.12,8.16 63.12,7.32 62.23,6.44 62.23,4.73 v1(61.36,3.85)
  BOTTOM w0.152: J1.C8 v1(61.36,3.85)
PRG0_PRU1GPO3_HDR: length 23.8
  TOP w0.152: U7.29 65.24,33.8 57.03,42.01 52.87,42.01 J4.11
PRG0_PRU1GPO4: length 28.6
  TOP w0.152: U7.10 60.24,18.33 59.56,17.65 57.87,17.65 56.81,16.6 56.81,15.2 57.02,14.99 57.02,14.1 61.93,9.19 61.93,6.3 59.91,4.29 59.91,4.29 59.66,4.03 59.66,4.03 58.74,3.12 55.81,3.12 v1(54.99,3.94)
  BOTTOM w0.152: J1.B13 54.99,3.84 v1(54.99,3.94)
PRG0_PRU1GPO4_HDR: length 17.8
  TOP w0.152: U7.41 59.26,28.34 59.26,32.95 56.34,35.86 v1(56.34,36.27)
  BOTTOM w0.152: J4.13 53.63,38.99 v1(56.34,36.27)
PRG0_PRU1GPO5: length 17.5
  TOP w0.152: v1(62.69,6.28) 63.31,6.28 64.01,6.99 64.01,15.61 66.17,17.78 66.45,17.78 66.74,18.07 U7.23
  BOTTOM w0.152: v1(62.69,6.28) 62.74,6.28 J1.D6
PRG0_PRU1GPO5_HDR: length 19.4
  TOP w0.152: U7.28 65.74,34.22 J4.15
PRG0_PRU1GPO6: length 18.3
  TOP w0.152: v1(57.65,7.77) 57.65,11.77 55.88,13.54 55.88,14.84 53.93,16.79 53.93,19.23 52.13,21.02 v1(52.13,21.57)
  BOTTOM w0.152: J1.E11 v1(57.65,7.77) ; U9.2 52.15,21.4 52.13,21.41 v1(52.13,21.57)
PRG0_PRU1GPO6_HDR: length 18.4
  BOTTOM w0.152: U9.48 52.65,30.93 58.71,36.99 J4.17
PRG0_PRU1GPO8: length 34.7
  TOP w0.152: v1(66.44,2.58) 66.88,3.03 v1(66.88,15.55)
  L03_SIG1 w0.152: v1(53.47,21.08) 53.6,20.95 53.6,20.95 53.97,20.57 63.17,20.57 65.42,18.32 65.42,17.01 v1(66.88,15.55)
  BOTTOM w0.152: v1(53.47,21.08) 53.47,21.4 53.23,21.64 52.91,21.64 52.54,22.01 51.72,22.01 51.15,21.43 U9.4 ; J1.B4 v1(66.44,2.58)
PRG0_PRU1GPO8_HDR: length 22.3
  BOTTOM w0.152: U9.47 52.15,27.09 52.47,26.76 53.03,26.76 53.44,27.17 53.44,31.08 61.25,38.89 J4.19
PRG0_PRU1GPO11: length 19.2
  TOP w0.152: v1(57.55,6.39) 56.55,7.39 56.55,9.85 49.64,16.76 v1(48.77,16.76)
  BOTTOM w0.152: J1.D11 v1(57.55,6.39) ; U9.8 49.15,19.05 48.77,18.67 v1(48.77,16.76)
PRG0_PRU1GPO11_HDR: length 59.6
  BOTTOM w0.152: U9.42 49.65,28.81 39.5,38.96 39.5,69.24 32.32,76.43 32.32,78.72 J5.1
PRG0_PRU1GPO12: length 23.2
  TOP w0.152: v1(45.72,16.64) 50.67,11.68 50.67,3.15 v1(51.23,2.59)
  BOTTOM w0.152: v1(51.23,2.59) 51.23,2.62 J1.B15 ; v1(45.72,16.64) 47.75,16.64 48.15,17.03 U9.10
PRG0_PRU1GPO12_HDR: length 59.5
  BOTTOM w0.152: J5.3 31.99,78.72 31.99,76.29 37.21,71.07 37.21,40.67 49.15,28.73 U9.41
PRG0_PRU1GPO13: length 38.7
  L03_SIG1 w0.152: v1(63.47,15.49) 63.13,15.83 63.13,18.58 62.16,19.56 47.18,19.56 44.39,16.76 v1(44.21,16.76)
  BOTTOM w0.152: U9.15 45.65,17.45 44.95,16.76 v1(44.21,16.76) ; v1(63.47,15.49) 64.14,14.83 64.14,7.55 63.93,7.05 63.93,6.36 J1.D5
PRG0_PRU1GPO13_HDR: length 60.2
  BOTTOM w0.152: U9.35 46.15,30.1 36.83,39.42 36.83,66.53 27.24,76.12 27.24,78.72 J5.5
PRG0_PRU1GPO14: length 22.3
  TOP w0.152: v1(55.15,8.59) 54.53,8.59 45.85,17.27 44,17.27 v1(43.49,16.76)
  BOTTOM w0.152: J1.E12 55.64,8.1 v1(55.15,8.59) ; U9.17 44.65,19.64 45.13,19.15 45.13,17.57 44.9,17.34 44.01,17.34 43.49,16.82 v1(43.49,16.76)
PRG0_PRU1GPO14_HDR: length 60.2
  BOTTOM w0.152: J5.7 26.91,78.72 26.91,75.99 36.53,66.37 36.53,39.3 36.58,39.24 36.58,39.22 45.65,30.14 U9.34
PRG0_PRU1GPO15: length 29.4
  TOP w0.152: v1(57.55,3.85) 56.25,5.16 56.25,9.55 v1(53.64,12.15)
  L03_SIG1 w0.152: v1(53.64,12.15) 47.38,12.15 42.25,17.27 v1(41.15,17.27)
  BOTTOM w0.152: v1(41.15,17.27) 41.53,17.27 42.67,18.41 42.67,20.37 U9.21 ; J1.C11 v1(57.55,3.85)
PRG0_PRU1GPO15_HDR: length 61.1
  BOTTOM w0.152: J5.9 22.16,78.72 22.16,76.8 36.2,62.76 36.2,36.12 43.15,29.17 U9.29
PRG0_PRU1GPO16: length 31.7
  L03_SIG1 w0.152: v1(41.08,17.91) 41.02,17.91 39.27,16.16 39.27,5.57 40.32,4.52 48.6,4.52 50.96,2.16 51.62,2.16 v1(52.47,1.31)
  BOTTOM w0.152: J1.A15 v1(52.47,1.31) ; v1(41.08,17.91) 41.15,17.91 41.65,18.41 U9.23
PRG0_PRU1GPO16_HDR: length 61
  BOTTOM w0.152: J5.11 21.86,78.7 21.86,76.67 35.89,62.64 35.89,36 35.94,35.95 35.94,35.92 42.65,29.21 U9.28
PRG1_PRU1GPO18: length 188
  L03_SIG1 w0.152: v1(55.01,7.66) 55.58,8.24 55.58,16.32 57.91,18.64 61.23,18.64 61.6,18.27 61.6,15.89 63.04,14.45 67.25,14.45 69.3,16.5 69.3,17.97 71.13,19.8 79.24,19.8 82.25,22.82 83.21,22.82 84.87,21.16 86.79,21.16 87.25,21.61 v1(87.25,22.61)
  BOTTOM w0.152: v1(87.25,22.61) 87.25,36.83 91.18,40.76 91.18,82.3 90.17,83.31 21.46,83.31 18.19,80.03 J5.13 ; J1.E13 v1(55.01,7.66)
PRG1_PRU1GPO19: length 145.5
  TOP w0.152: v1(44.45,66.68) 60.83,66.68 63.01,64.49 63.01,39.66 68.18,34.5 68.18,25.92 66.37,24.1 55.14,24.1 54.23,23.19 54.23,22.73 53.67,22.17 v1(53.21,22.17)
  L03_SIG1 w0.152: J5.15 18.62,82.8 33.78,82.8 35.69,80.9 35.69,75.69 36.83,74.55 44.83,74.55 45.85,73.53 45.85,67.69 44.83,66.68 v1(44.45,66.68)
  BOTTOM w0.152: v1(53.21,22.17) 53.65,22.17 53.96,21.86 53.96,17.51 51.2,14.75 51.2,9.76 52.2,8.76 53.44,8.76 53.72,8.48 53.72,5.49 54.11,5.1 55.03,5.1 J1.C12
RX_1: length 183.5
  TOP w0.152: TP8.1 124.12,138.83 128.16,142.88 130.82,142.88 v1(131.36,142.34)
  L03_SIG1 w0.152: v1(80.23,26.16) 80.42,25.97 80.44,25.97 80.63,25.78 81.28,25.78 81.92,26.42 101.71,26.42 116.31,41.02 126.36,41.02 140.44,55.1 140.44,70.08 141.99,71.63 141.99,136.12 135.78,142.34 v1(131.36,142.34)
  BOTTOM w0.152: U27.3 133.5,141.17 132.53,141.17 v1(131.36,142.34) ; U2.45 80.39,28.57 80.39,26.33 v1(80.23,26.16)
RX_2: length 155.1
  TOP w0.152: TP11.1 124,113.38 128.04,117.42 130.71,117.42 v1(131.25,116.88)
  L03_SIG1 w0.152: v1(77.98,26.67) 78.74,26.67 80.52,28.45 99.44,28.45 116.46,45.47 129.51,45.47 138.96,54.92 138.96,109.98 134.65,114.3 133.83,114.3 v1(131.25,116.88)
  BOTTOM w0.152: v1(77.98,26.67) 78.87,26.67 79.89,27.69 U2.44 ; v1(131.25,116.88) 132.42,115.71 133.38,115.71 U28.3
RX_3: length 133.9
  TOP w0.152: TP14.1 124,87.98 127.5,91.48 v1(131.25,91.48) 134.51,94.74 137.42,94.74 v1(137.67,95)
  L03_SIG1 w0.152: v1(77.98,29.84) 78.45,30.31 83.61,30.31 83.96,29.96 98.29,29.96 116.71,48.39 131.57,48.39 138.35,55.17 138.35,94.31 v1(137.67,95)
  BOTTOM w0.152: v1(131.25,91.48) 132.42,90.31 133.38,90.31 U30.3 ; U2.39 77.39,29.38 77.85,29.84 v1(77.98,29.84)
RX_4: length 88.5
  TOP w0.152: v1(131.38,65.7) 128.2,65.7 124.69,62.2 TP17.1
  L03_SIG1 w0.152: v1(131.38,65.7) 127.8,65.7 126.49,64.39 126.49,63.37 99.8,36.68 77.96,36.68 v1(76.58,35.31)
  BOTTOM w0.152: v1(76.58,35.31) 75.95,34.67 75.95,33.15 76.76,32.33 76.76,29.76 76.89,29.64 U2.38 ; U29.3 133.51,64.53 132.71,64.53 131.55,65.7 v1(131.38,65.7)
RX_5: length 76.5
  TOP w0.152: TP20.1 102.47,62.2 v1(105.98,65.7)
  L03_SIG1 w0.152: v1(73.41,37.85) 74.04,37.85 75.26,39.07 96.03,39.07 105.28,48.32 105.28,62.74 105.98,63.43 v1(105.98,65.7)
  BOTTOM w0.152: U31.3 108.11,64.53 107.14,64.53 v1(105.98,65.7) ; U2.32 73.89,37.37 v1(73.41,37.85)
RX_6: length 106.4
  TOP w0.152: 96.99,88.1 99.95,85.15 99.95,81.41 106.94,74.42 106.94,64.14 98.46,55.66 98.46,55.57 93.18,50.29 71.38,50.29 69.9,48.82 69.9,42.57 72.22,40.24 72.22,31.26 v1(72.88,30.59) ; 96.99,88.1 99.95,91.06 105.43,91.06 v1(105.98,91.61) ; 96.99,88.1 TP23.1
  BOTTOM w0.152: U32.3 108.11,90.44 107.14,90.44 v1(105.98,91.61) ; U2.31 73.39,30.09 v1(72.88,30.59)
RX_7: length 133.8
  TOP w0.152: v1(105.98,116.5) 102.23,116.5 98.73,113 TP26.1
  L03_SIG1 w0.152: v1(105.98,116.5) 93.85,104.37 93.85,101.61 93.17,100.93 93.17,81.46 103.13,71.5 103.13,58.8 92.2,47.88 92.2,42.17 90.42,40.39 73.79,40.39 v1(71.38,37.97)
  BOTTOM w0.152: U2.26 70.89,29.88 71.58,30.57 71.58,37.77 v1(71.38,37.97) ; U33.3 108.11,115.33 107.14,115.33 v1(105.98,116.5)
RX_8: length 171.8
  TOP w0.152: v1(103.38,142.24) 103.38,140.72 101.19,138.52 TP29.1
  L03_SIG1 w0.152: v1(70.23,35.05) 72.39,37.21 72.39,38.08 73.96,39.65 96.18,39.65 104.78,48.24 104.78,62.74 105.28,63.25 105.28,72.26 100.75,76.79 100.75,93.13 113.72,106.1 113.72,138.69 110.17,142.24 v1(103.38,142.24)
  BOTTOM w0.152: U2.25 70.39,29.84 69.47,30.76 69.47,34.67 69.85,35.05 v1(70.23,35.05) ; U34.3 108.11,140.86 107.14,140.86 105.76,142.24 v1(103.38,142.24)
SOC_I2C0_SCL: length 45.6
  TOP w0.152: v1(90.75,31.62) 90.79,31.67 U1.6
  BOTTOM w0.152: J1.E1 71.38,8.8 79.03,8.8 85.22,14.99 90.81,14.99 90.98,15.16 90.98,28.77 91.18,28.97 91.18,30.57 90.75,31.01 v1(90.75,31.62)
SOC_I2C0_SDA: length 39.2
  TOP w0.152: U1.5 91.49,30.4 91.48,30.4 v1(90.75,30.4)
  BOTTOM w0.152: J1.E2 71.08,9.77 75.18,9.77 90.68,25.27 90.68,28.9 90.84,29.06 90.84,30.31 v1(90.75,30.4)
SOC_SPI1_CLK: length 19.8
  TOP w0.152: U17.15 77.39,12.26 v1(70.25,5.12)
  BOTTOM w0.152: J1.C1 v1(70.25,5.12)
SOC_SPI1_CLK_HDR: length 27.4
  TOP w0.152: U17.35 76.89,29.36 77.63,30.1 77.63,41.95 77.54,42.03 77.54,44.18 77.63,44.26 77.63,46.27 76.87,47.03 72.98,47.03 72.55,46.6 72.55,44.6 J9.5
SOC_SPI1_CLK_SE/LED: length 74.4
  TOP w0.152: v1(125.22,32.38) 127.11,34.28 U26.3 ; v1(95.82,27.34) 78.7,27.34 78.39,27.65 U17.32 ; R119.2 v1(104.84,16.58)
  BOTTOM w0.152: v1(104.84,16.58) 101.15,16.58 95.82,21.91 v1(95.82,27.34) 95.82,28.75 96.82,29.75 111.54,29.75 114.17,32.38 v1(125.22,32.38)
SOC_SPI1_CS0: length 17.5
  TOP w0.152: v1(70.25,6.39) 74.89,11.03 U17.10
  BOTTOM w0.152: J1.D1 v1(70.25,6.39)
SOC_SPI1_CS0_HDR: length 14.8
  TOP w0.152: J9.7 73.87,28.59 U17.41
SOC_SPI1_CS0_SE: length 37.4
  TOP w0.152: U17.38 75.39,24.89 76.14,24.13 v1(78.74,24.13) ; R122.1 v1(104.84,17.81)
  L03_SIG1 w0.152: v1(104.84,17.81) 103.73,17.81 97.2,24.34 78.95,24.34 v1(78.74,24.13)
SOC_SPI1_CS1: length 17.6
  TOP w0.152: v1(68.98,6.39) 73.27,10.69 73.27,19.33 73.89,19.94 U17.8
  BOTTOM w0.152: J1.D2 v1(68.98,6.39)
SOC_SPI1_CS1_HDR: length 20.1
  TOP w0.152: J9.9 75.31,44.49 73.42,44.49 72.52,43.59 72.52,40.38 72.53,40.37 72.53,33.52 73.39,32.66 U17.42
SOC_SPI1_MISO: length 26.1
  TOP w0.152: U17.2 70.89,21.97 70.72,22.14 70.02,22.14 69.69,21.81 69.69,16.86 67.28,14.45 67.28,3.68 68.8,2.15 69.82,2.15 v1(70.25,2.58)
  BOTTOM w0.152: J1.B1 v1(70.25,2.58)
SOC_SPI1_MISO_HDR: length 16.5
  TOP w0.152: U17.48 70.39,29.44 69.47,30.35 69.47,37.42 66.25,40.63 J9.1
SOC_SPI1_MISO_SE: length 40.6
  TOP w0.152: U38.4 101.71,15.66 R120.2 98.55,15.62 90.68,23.5 85.35,23.5 83.68,21.83 82.41,21.83 81.37,22.88 73.71,22.88 71.89,24.7 U17.45
SOC_SPI1_MOSI: length 21.2
  TOP w0.152: U17.4 71.89,17.64 68.25,14 68.25,3.31 v1(68.98,2.58)
  BOTTOM w0.152: J1.B2 v1(68.98,2.58)
SOC_SPI1_MOSI_HDR: length 16.3
  TOP w0.152: U17.47 70.89,29.45 70.11,30.23 70.11,33.15 70.89,33.93 70.89,40.4 68.79,42.49 J9.3
SOC_SPI1_MOSI_LED: length 70
  TOP w0.152: v1(93.73,25.15) 93.71,25.13 81.8,25.13 79.95,23.28 73.95,23.28 72.39,24.84 U17.44 ; v1(126.24,34.8) 126.35,34.91 U26.2
  BOTTOM w0.152: v1(126.24,34.8) 126.2,34.84 113.84,34.84 110.3,31.3 95.45,31.3 93.62,29.47 93.62,27.96 93.42,27.76 93.42,25.32 93.6,25.15 v1(93.73,25.15)
TX_1: length 198.9
  TOP w0.152: v1(126.88,142.42) 126.55,142.42 124.61,140.49 TP7.1
  L03_SIG1 w0.152: v1(69.85,23.62) 70.74,23.62 70.99,23.88 76.56,23.88 80.75,28.07 100.97,28.07 116.59,43.69 128.17,43.69 139.27,54.79 139.27,134.65 136.25,137.67 130.64,137.67 126.88,141.43 v1(126.88,142.42)
  BOTTOM w0.152: U4.45 65.74,26.97 67.57,25.15 68.2,25.15 69.72,23.62 v1(69.85,23.62) ; D16.2 126.84,142.39 v1(126.88,142.42) 127.71,143.26 131.13,143.26 132.73,141.66 U27.4
TX_2: length 172.9
  TOP w0.152: v1(126.76,116.97) 124.12,116.97 TP10.1
  L03_SIG1 w0.152: v1(68.32,23.7) 68.34,23.71 68.55,23.71 69.55,24.71 73.23,24.71 77.27,28.75 98.22,28.75 116.08,46.61 130.23,46.61 138.66,55.04 138.66,109.86 134.52,114 132.51,114 129.54,116.97 v1(126.76,116.97)
  BOTTOM w0.152: D17.2 126.74,116.94 v1(126.76,116.97) 127.6,117.8 131.01,117.8 132.61,116.2 U28.4 ; U4.44 65.24,26.2 67.74,23.7 v1(68.32,23.7)
TX_3: length 123
  TOP w0.152: v1(126.76,91.57) 126.49,91.57 124.56,89.63 TP13.1
  L03_SIG1 w0.152: v1(126.76,91.57) 127.51,91.57 128.65,90.42 128.65,68.95 97,37.29 76.89,37.29 67.82,28.22 67.82,27.43 66.78,26.4 v1(64.71,26.4)
  BOTTOM w0.152: U4.39 62.74,26.94 63.29,26.4 v1(64.71,26.4) ; U30.4 132.61,90.8 131.09,92.33 127.53,92.33 v1(126.76,91.57) 126.74,91.54 D18.2
TX_4: length 99.1
  TOP w0.152: v1(126.89,65.78) 124.25,65.78 TP16.1
  L03_SIG1 w0.152: v1(126.89,65.78) 126.75,65.78 97.95,36.99 77.02,36.99 72.01,31.98 72.01,28.83 70.79,27.61 69.14,27.61 66.68,25.15 v1(63.5,25.15)
  BOTTOM w0.152: v1(63.5,25.15) 62.24,26.4 U4.38 ; D19.2 126.89,65.78 v1(126.89,65.78) 127.23,66.13 131.63,66.13 132.74,65.02 U29.4
TX_5: length 84.2
  TOP w0.152: v1(101.49,65.78) 98.85,65.78 TP19.1
  L03_SIG1 w0.152: v1(101.49,65.78) 100.2,65.78 91.24,56.82 91.24,42.5 90.42,41.68 73.61,41.68 68.23,36.3 68.23,32.28 66.11,30.17 59.05,30.17 v1(58.79,30.43)
  BOTTOM w0.152: U4.32 59.24,29.93 58.79,30.38 v1(58.79,30.43) ; D20.2 101.47,65.76 v1(101.49,65.78) 102.33,66.62 105.74,66.62 107.34,65.02 U31.4
TX_6: length 121.8
  TOP w0.152: TP22.1 98.85,91.69 v1(101.49,91.69)
  L03_SIG1 w0.152: v1(59.06,26.92) 60.68,28.55 66.86,28.55 76.76,38.46 96.28,38.46 112.56,54.73 112.56,73.24 101.49,84.31 v1(101.49,91.69)
  BOTTOM w0.152: U4.31 58.74,27.24 v1(59.06,26.92) ; D21.2 101.47,91.67 v1(101.49,91.69) 102.33,92.53 105.74,92.53 107.34,90.93 U32.4
TX_7: length 137.7
  TOP w0.152: v1(101.49,116.58) 98.85,116.58 TP25.1
  L03_SIG1 w0.152: v1(101.49,116.58) 100.84,116.58 91.7,107.44 91.7,57.91 90.93,57.15 90.93,42.62 90.3,41.99 72.85,41.99 67.92,37.06 67.92,32.41 65.98,30.47 60.2,30.47 59.13,31.55 57.96,31.55 56.95,30.53 v1(56.77,30.53)
  BOTTOM w0.152: U33.4 107.34,115.82 105.74,117.42 102.33,117.42 v1(101.49,116.58) 101.47,116.56 D22.2 ; U4.26 56.24,30.25 56.52,30.53 v1(56.77,30.53)
TX_8: length 160.5
  TOP w0.152: TP28.1 98.87,142.13 v1(100.72,142.13)
  L03_SIG1 w0.152: v1(54.99,30.86) 56.29,32.16 59.38,32.16 59.71,31.83 66.47,31.83 67.17,32.52 67.17,37.43 72.46,42.72 72.46,46.5 76.89,50.93 81.56,50.93 90.43,59.79 90.43,92.58 90.81,92.96 90.81,109.63 105.53,124.34 105.53,136.54 100.84,141.22 100.84,142.01 v1(100.72,142.13)
  BOTTOM w0.152: D23.2 100.97,141.45 100.72,141.7 v1(100.72,142.13) 101.54,142.95 105.74,142.95 107.34,141.35 U34.4 ; U4.25 55.74,30.11 v1(54.99,30.86)
N16728800: length 4.9
  TOP w0.152: R104.1 87.05,95.56 U35.11
N16729761: length 4.9
  TOP w0.152: U36.11 72.48,95.56 R107.1
N16731521: length 11.6
  TOP w0.152: R111.2 119.65,15.65 119.65,16.41 v1(118.34,17.72) U37.3
  BOTTOM w0.152: C95.1 119.57,14.49 118.34,15.73 v1(118.34,17.72)
N16731525: length 9.9
  TOP w0.152: R112.2 118.34,18.83 v1(118.34,19.02) U37.5
  BOTTOM w0.152: C96.1 120.46,16.38 118.34,18.5 v1(118.34,19.02)
N16731545: length 8.8
  TOP w0.152: U37.7 v1(118.34,20.32) 120.21,18.44 R113.2
  BOTTOM w0.152: v1(118.34,20.32) 120.21,18.44 C97.1
N16731549: length 8.2
  TOP w0.152: U37.9 v1(118.34,21.62) 119.48,20.48 R114.2
  BOTTOM w0.152: C98.1 119.48,20.48 v1(118.34,21.62)
N16731553: length 7.8
  TOP w0.152: R115.2 118.97,22.29 v1(118.34,22.92) U37.11
  BOTTOM w0.152: C99.1 118.97,22.29 v1(118.34,22.92)
N16731557: length 5.9
  TOP w0.152: U37.18 v1(108.33,22.92) 107.66,23.59 R116.2
  BOTTOM w0.152: v1(108.33,22.92) 107.66,23.59 C100.1
N16731561: length 5.5
  TOP w0.152: R117.2 108.25,21.54 v1(108.33,21.62) U37.20
  BOTTOM w0.152: C101.1 108.25,21.54 v1(108.33,21.62)
N16731565: length 5.9
  TOP w0.152: U37.22 v1(108.33,20.32) 107.5,19.49 R118.2
  BOTTOM w0.152: v1(108.33,20.32) 107.5,19.49 C102.1
N16731823: length 7.8
  TOP w0.152: U37.1 117.06,16.42 118.32,15.15 118.32,13.65 120.53,11.44 R123.2
N16731831: length 7.3
  TOP w0.152: U37.2 117.55,17.07 119.06,15.56 119.06,14.43 120.73,12.76 R124.2
N16731839: length 4.1
  TOP w0.152: U37.24 108.96,19.02 107.75,17.81 R122.2
N16731843: length 5.1
  TOP w0.152: R125.1 120.84,24.23 116.14,24.23 U37.13
N16732201: length 12
  TOP w0.152: U37.23 109.04,19.67 107.98,18.61 103.79,18.61 103.41,18.23 U38.2
N16798390: length 4.5
  TOP w0.152: R121.2 109.44,17.72 U37.26
N16812824: length 1
  TOP w0.152: D10.1 D12.2
N16812834: length 1.5
  TOP w0.152: D12.1 D14.2
N16813069: length 1
  TOP w0.152: D9.1 D11.2
N16813071: length 1
  TOP w0.152: D11.1 D13.2
N16970041: length 1.3
  BOTTOM w0.152: U30.6 137.68,91.3 R82.1
N16970059: length 1.4
  BOTTOM w0.152: Q7.3 D4.1
N17109412: length 4.3
  TOP w0.152: U37.25 109.18,18.37 107.39,16.58 R119.1
N17175087: length 1.3
  BOTTOM w0.152: U27.6 137.79,142.16 R74.1
N17175103: length 1.4
  BOTTOM w0.152: Q4.3 D1.1
N17184096: length 1.3
  BOTTOM w0.152: R75.1 137.68,116.7 U28.6
N17184112: length 1.4
  BOTTOM w0.152: Q5.3 D2.1
N17184793: length 1.3
  BOTTOM w0.152: U29.6 137.8,65.52 R80.1
N17184817: length 1.4
  BOTTOM w0.152: Q6.3 D3.1
N17188199: length 2.5
  TOP w0.152: J11.2 89.68,19.17 R72.2
N17189922: length 4.8
  TOP w0.152: U26.23 133.6,34.91 133.06,35.46 133.06,37.54 R73.1
N17190440: length 1.5
  TOP w0.152: R64.2 116.69,36.95 LD1.2
N17190442: length 2.9
  TOP w0.152: LD1.1 118.6,35.19 Q1.3
N17190473: length 1.5
  TOP w0.152: R65.2 111.01,37.02 LD2.2
N17190482: length 2.9
  TOP w0.152: LD2.1 112.62,35.56 112.62,34.67 112.92,34.37 Q2.3
N17190504: length 2.9
  TOP w0.152: LD5.1 107.03,34.35 107.35,34.04 Q3.3
N17190506: length 1.5
  TOP w0.152: LD5.2 105.43,37.09 R68.2
N17190525: length 1.4
  TOP w0.152: Q3.1 103.76,33.88 R71.2
N17190539: length 1.7
  TOP w0.152: R67.2 100.65,32.96 LD4.2
N17190541: length 1.7
  TOP w0.152: LD3.2 R66.2
N17194207: length 1.3
  BOTTOM w0.152: R87.1 112.4,91.43 U32.6
N17194223: length 1.4
  BOTTOM w0.152: Q9.3 D5.1
N17194517: length 1.3
  BOTTOM w0.152: R86.1 112.4,65.52 U31.6
N17194572: length 1.4
  BOTTOM w0.152: Q8.3 D6.1
N17194628: length 1.3
  BOTTOM w0.152: R92.1 112.4,141.85 U34.6
N17194647: length 1.4
  BOTTOM w0.152: Q10.3 D7.1
N17196536: length 1.3
  BOTTOM w0.152: R93.1 112.4,116.32 U33.6
N17196560: length 1.4
  BOTTOM w0.152: Q11.3 D8.1
N17284137: length 1.3
  BOTTOM w0.152: Q4.1 126.84,138.88 D16.1
N17284170: length 1.3
  BOTTOM w0.152: Q5.1 D17.1
N17284203: length 1.4
  BOTTOM w0.152: Q7.1 D18.1
N17284241: length 1.2
  BOTTOM w0.152: D19.1 126.87,63.4 Q6.1
N17284279: length 1.3
  BOTTOM w0.152: Q8.1 101.47,62.23 D20.1
N17284317: length 1.3
  BOTTOM w0.152: Q9.1 101.47,89.43 D21.1
N17284361: length 1.4
  BOTTOM w0.152: D22.1 101.47,113.84 101.47,113.84 Q11.1
N17284397: length 1.3
  BOTTOM w0.152: D23.1 101.47,138.55 Q10.1
N169701040: length 1.5
  BOTTOM w0.152: R85.1 128.67,88.04 Q7.2
N169703320: length 2.2
  TOP w0.152: LD22.2 R131.2
N171751400: length 1.5
  BOTTOM w0.152: R78.1 128.79,138.9 Q4.2
N171841470: length 1.5
  BOTTOM w0.152: R79.1 128.67,113.44 Q5.2
N171847351: length 1.5
  BOTTOM w0.152: R84.1 128.8,62.26 Q6.2
N171943770: length 1.5
  BOTTOM w0.152: Q8.2 103.4,62.26 R90.1
